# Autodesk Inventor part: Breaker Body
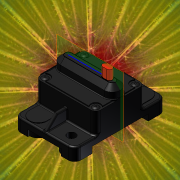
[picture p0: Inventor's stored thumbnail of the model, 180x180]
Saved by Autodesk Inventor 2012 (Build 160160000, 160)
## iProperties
Shininess: 64.0
Angle Display Precision: 2
Document Length Units: 11272
Document Angle Units: 11279
Document Time Units: 11290
Document Mass Units: 11286
Document Length Units Precision: 3
Document Angle Units Precision: 2
Compacted: False
Created: 2004-01
Part Number: Breaker Body
Material: Phenolic
Document SubType Name: Modeling
Designer: t8558es
Density: 1 g/cm^3
Density: 0.0
Volumn: 0.0
Area: 0.0
PropertySet Name: Model Information
Control State: 0
Master: False
Checked Out: False
Author: t8558es
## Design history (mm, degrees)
sketch "Sketch1"
  geometry: L1 (-24.13, 36.703)-(24.13, 36.703); L2 (24.13, 36.703)-(24.13, -36.703); L3 (24.13, -36.703)-(-24.13, -36.703); L4 (-24.13, -36.703)-(-24.13, 36.703); 1 further point
  constraints: 8 end point, 2 parallel, 1 horizontal, 1 perpendicular, 1 other
  dimensions: "d0" = 48.26 distance of L1.start L1.end; "d1" = 73.406 distance of L1.end L2.end; "d2" = 24.13 distance from line of point (0, 0) L4 (= 0.5 x d0); "d3" = 36.703 distance from line of L3 point (0, 0) (= 0.5 x d1)
extrude "Extrusion1" new body sketch "Sketch1" distance "d4" = 5.08; taper "d5" = 0 deg
fillet "Fillet1" dims "d6" = 5.08
sketch "Sketch2"
  geometry: L1 (24.13, 31.623)-(24.13, -31.623) reference; L2 (-24.13, -31.623)-(-24.13, 31.623) reference; L3 (-24.13, 19.685)-(24.13, 19.685); L4 (-24.13, -19.685)-(24.13, -19.685); L5 (0, 0)-(0, 19.685); L6 (0, 0)-(0, -19.685)
  constraints: 8 end point, 4 point on line, 2 midpoint, 1 collinear, 1 parallel, 1 perpendicular, 1 other
  dimensions: "d7" = 39.37 distance between parallel lines of L4 L3
extrude "Extrusion2" join sketch "Sketch2" distance "d8" = 17.526; taper "d9" = 0 deg
fillet "Fillet2" dims "d10" = 3.81
sketch "Sketch3"
  geometry: L1 (-19.05, 36.703)-(19.05, 36.703) reference; L2 (-24.13, 15.875)-(-24.13, 31.623) reference; 1 further point
  dimensions: "d11" = 10.795 distance from line of point (-13.335, 28.321) L2; "d12" = 8.382 distance from line of L1 point (-13.335, 28.321)
hole "Hole1" sketch "Sketch3" at (-13.335, 28.321) diameter "d13" = 6.604; stored, may be unused: countersink angle "d17" = 82 deg, drill point angle "d19" = 118 deg; dims "d14" = 12.7, "d15" = 9.525, "d16" = 6.35, "d18" = 19.05
sketch "Sketch5"
  geometry: L1 (24.13, -31.623)-(24.13, 31.623) reference; L2 (19.05, 36.703)-(-19.05, 36.703) reference; L3 (13.335, 35.433)-(13.335, 36.703); L4 (17.391, 22.479)-(24.13, 22.479); C1 r 3.302 at (13.335, 28.321) reference; A1 r 5.08 centre (19.05, 31.623) between (24.13, 31.623) and (19.05, 36.703) reference; A2 r 7.112 centre (13.335, 28.321) between (13.335, 35.433) and (17.391, 22.479)
  constraints: 4 end point, 3 point on line, 2 perpendicular, 2 point on circle, 1 centre point, 1 coincident
  dimensions: "d20" = 14.224 diameter of A2; "d21" = 14.224 distance between parallel lines of L2 L4
extrude "Extrusion3" join sketch "Sketch5" distance "d23" = 5.08; taper "d24" = 0 deg
mirror "Mirror3"
mirror "Mirror4"
sketch "Sketch6"
  geometry: L1 (24.13, 15.875)-(24.13, -15.875) reference; L2 (-24.13, -15.875)-(-24.13, 15.875) reference; L3 (-24.13, 6.477)-(24.13, 6.477); L4 (-24.13, -6.477)-(24.13, -6.477); L5 (0, 0)-(0, -6.477); L6 (0, 0)-(0, 6.477)
  constraints: 8 end point, 4 point on line, 2 midpoint, 2 perpendicular, 1 collinear, 1 other
  dimensions: "d25" = 12.954 distance between parallel lines of L4 L3
extrude "Extrusion4" join sketch "Sketch6" distance "d26" = 8.89; taper "d27" = 0 deg
fillet "Fillet3" dims "d28" = 6.477
chamfer "Chamfer1" distance "d29" = 3.81; stored, may be unused: second distance "d30" = 3.81, angle "d47" = 45 deg
sketch "Sketch7"
  geometry: L1 (-17.653, 2.159)-(-10.033, 2.159); L2 (-10.033, 2.159)-(-10.033, -2.159); L3 (-10.033, -2.159)-(-17.653, -2.159); L4 (-17.653, -2.159)-(-17.653, 2.159); A1 r 2.667 centre (-17.653, 0) between (-17.653, 2.667) and (-17.653, -2.667) reference
  constraints: 8 end point, 2 parallel, 1 horizontal, 1 midpoint, 1 perpendicular
  dimensions: "d31" = 4.318 distance of L1.end L2.end; "d32" = 7.62 distance of L2.end L3.end; "d33" = 2.159 distance from line of L1 A1.centre (= 0.5 x d31)
extrude "Button" join sketch "Sketch7" distance "d34" = 7.62; taper "d35" = 0 deg
fillet "Fillet4" dims "d36" = 2.159 (= 0.5 x d31)
fillet "Fillet7" dims "d46" = 1.27
sketch "Sketch8"
  geometry: L1 (-20.32, 19.685)-(20.32, 19.685) reference; L2 (-19.05, 36.703)-(19.05, 36.703) reference; L3 (-1.27, 36.703)-(-1.27, 19.685); L4 (1.27, 36.703)-(1.27, 19.685); 1 further point
  constraints: 4 end point, 4 point on line, 1 parallel, 1 perpendicular, 1 other
  dimensions: "d37" = 2.54 distance between parallel lines of L4 L3; "d38" = 1.27 distance from line of point (0, 0) L4 (= 0.5 x d37)
extrude "Extrusion6" join sketch "Sketch8" distance "d39" = 8.89; taper "d40" = 0 deg
chamfer "Chamfer2" distance "d41" = 8.89; stored, may be unused: second distance "d42" = 8.89, angle "d48" = 45 deg
fillet "Fillet5" dims "d43" = 1.27
mirror "Mirror5"
fillet "Fillet6" dims "d44" = 1.27, "d45" = 0.635
sketch "Sketch9"
  geometry: L1 (24.13, 2.938)-(24.13, 15.875) reference; L2 (-20.32, 19.685)-(20.32, 19.685) reference; L3 (-24.13, 2.938)-(-24.13, 15.875) reference; L4 (-22.86, 4.844)-(22.86, 4.844); L5 (22.86, 4.844)-(22.86, 18.415); L6 (22.86, 18.415)-(-22.86, 18.415); L7 (-22.86, 18.415)-(-22.86, 4.844); L8 (24.13, 2.938)-(24.13, 15.875) reference; L9 (-20.32, 19.685)-(20.32, 19.685) reference; L10 (-24.13, 2.938)-(-24.13, 15.875) reference; L11 (17.653, 7.112)-(-17.653, 7.112) reference; L12 (24.13, 2.938)-(24.129, 15.972); L13 (20.32, 19.685)-(-20.32, 19.685); L14 (-24.13, 15.875)-(-24.13, 2.938); A1 r 3.81 centre (20.32, 15.875) between (24.13, 15.875) and (20.32, 19.685) reference; A2 r 3.81 centre (-20.32, 15.875) between (-20.32, 19.685) and (-24.13, 15.875) reference; A3 r 7.112 centre (-17.653, 0) between (-17.653, 7.112) and (-24.13, 2.938) reference; A4 r 3.81 centre (-20.32, 15.875) between (-20.32, 19.685) and (-24.13, 15.875); A5 r 3.81 centre (20.32, 15.875) between (24.129, 15.972) and (20.32, 19.685); A6 r 7.112 centre (17.653, 0) between (24.13, 2.938) and (17.653, 7.112) reference; A7 r 3.81 centre (20.32, 15.875) between (24.13, 15.875) and (20.32, 19.685) reference; A8 r 3.81 centre (-20.32, 15.875) between (-20.32, 19.685) and (-24.13, 15.875) reference; A9 r 7.112 centre (-17.653, 0) between (-17.653, 7.112) and (-24.13, 2.938) reference; A10 r 7.112 centre (17.653, 0) between (24.13, 2.938) and (22.86, 4.844); A11 r 3.81 centre (20.32, 15.875) between (24.13, 15.875) and (20.32, 19.685); A12 r 3.81 centre (-20.32, 15.875) between (-20.32, 19.685) and (-24.13, 15.875); A13 r 7.112 centre (-17.653, 0) between (-22.86, 4.844) and (-24.13, 2.938)
  constraints: 14 end point, 14 point on circle, 12 tangent, 6 centre point, 4 equal length, 3 concentric, 3 point on line, 2 coincident, 1 horizontal, 1 perpendicular
  dimensions: "d52" = 1.27 distance between parallel lines of L2 L6; "d53" = 1.27 distance between parallel lines of L1 L5; "d54" = 1.27 distance between parallel lines of L3 L7
extrude "Extrusion7" cut sketch "Sketch9" distance "d55" = 0.762; taper "d56" = 0 deg
sketch "Sketch10"
  geometry: L1 (-17.48, 18.415)-(17.48, 18.415) reference; C1 r 2.54 at (20.32, 15.875); C2 r 2.54 at (-20.32, 15.875); A1 r 3.81 centre (-20.32, 15.875) between (-22.86, 13.035) and (-17.48, 18.415) reference; A2 r 3.81 centre (20.32, 15.875) between (17.48, 18.415) and (22.86, 13.035) reference
  constraints: 2 centre point, 2 coincident, 1 tangent
  dimensions: "d57" = 5.08 diameter of C1; "d58" = 5.08 diameter of C2 (derived)
extrude "Extrusion8" join sketch "Sketch10" stored distance "d59" = 0.762; taper "d60" = 0 deg
fillet "Fillet8" dims "d61" = 2.54
sketch "Sketch11"
  geometry: L1 (-12.192, -2.159)-(-15.494, -2.159) reference; L2 (-15.494, 2.159)-(-12.192, 2.159) reference; L3 (-17.653, 2.667)-(17.653, 2.667) reference; L4 (17.653, -2.667)-(-17.653, -2.667) reference; L5 (17.653, 0)-(-16.76, 0); A1 r 2.159 centre (-15.494, 0) between (-15.494, 2.159) and (-15.494, -2.159) reference; A2 r 2.159 centre (-12.192, 0) between (-12.192, -2.159) and (-12.192, 2.159) reference; A3 r 2.667 centre (-17.653, 0) between (-17.653, 2.667) and (-17.653, -2.667) reference; A4 r 2.667 centre (17.653, 0) between (17.653, -2.667) and (17.653, 2.667) reference
  constraints: 2 end point, 1 parallel
workplane "Work Plane1"
node "Sketch12"
workplane "Work Plane2"
mirror "Mirror7"
fillet "Fillet9" dims "d63" = 2.54
sketch "Sketch13"
  geometry: L1 (1.719, 35.433)-(19.05, 35.433) reference; L2 (20.32, 20.955)-(1.905, 20.955) reference; L3 (13.335, 28.321)-(21.7, 28.321); L4 (13.335, 28.321)-(2.495, 28.321); L5 (6.223, 28.321)-(6.223, 20.955); L6 (20.447, 28.321)-(20.32, 20.955); C1 r 3.302 at (13.335, 28.321) reference; C2 r 6.35 at (13.335, 28.321) reference; C3 r 6.35 at (13.335, 28.321); A1 r 7.112 centre (13.335, 28.321) between (6.223, 28.321) and (20.447, 28.321)
  constraints: 8 end point, 3 point on line, 2 centre point, 2 coincident, 2 point on circle, 2 tangent, 1 collinear, 1 concentric, 1 parallel, 1 perpendicular
extrude "Extrusion9" join sketch "Sketch13" distance "d64" = 0.508; taper "d65" = 0 deg
sketch "Sketch14"
  geometry: L1 (-1.719, -35.433)-(-19.05, -35.433) reference; L2 (-20.32, -20.955)-(-1.905, -20.955) reference; L3 (-13.335, -28.321)-(-21.971, -28.321); L4 (-13.335, -28.321)-(-2.859, -28.321); L5 (-6.223, -28.321)-(-6.223, -20.955); L6 (-20.447, -28.321)-(-20.447, -20.953); C1 r 3.302 at (-13.335, -28.321) reference; C2 r 6.35 at (-13.335, -28.321) reference; A1 r 5.08 centre (-20.32, -15.875) between (-22.86, -20.274) and (-20.32, -20.955) reference; A2 r 7.112 centre (-13.335, -28.321) between (-6.223, -28.321) and (-20.447, -28.321)
  constraints: 8 end point, 3 point on circle, 3 point on line, 3 tangent, 2 parallel, 1 centre point, 1 coincident, 1 collinear, 1 perpendicular
extrude "Extrusion10" join sketch "Sketch14" distance "d66" = 0.508; taper "d67" = 0 deg
sketch "Sketch15"
  geometry: L1 (-5.47, -21.284)-(-2.721, -21.284); L2 (-2.721, -21.284)-(-2.721, -48.102); L3 (-2.721, -48.102)-(-5.47, -48.102); L4 (-5.47, -48.102)-(-5.47, -21.284)
  constraints: 2 other
emboss "Emboss1" sketch "Sketch15" dims "d7" = 39.37, "d68" = 0.254, "d69" = 0
sketch "Sketch16"
  geometry: C1 r 1.27 at (19.05, -31.623); A1 r 3.81 centre (19.05, -31.623) between (19.05, -35.433) and (22.86, -31.623) reference
  constraints: 1 centre point, 1 coincident
  dimensions: "d84" = 2.54 diameter of C1
extrude "Extrusion11" cut sketch "Sketch16" distance "d70" = 0.0254; taper "d71" = 0 deg
sketch "Sketch17"
  geometry: L1 (5.335, 21.387)-(2.781, 21.387); L2 (2.781, 21.387)-(2.781, 34.472); L3 (2.781, 34.472)-(5.335, 34.472); L4 (5.335, 34.472)-(5.335, 21.387)
  constraints: 2 other
emboss "Emboss2" sketch "Sketch17" dims "d7" = 39.37, "d72" = 0.254, "d73" = 0
sketch "Sketch18"
  geometry: L1 (-17.48, -18.415)-(17.48, -18.415) reference; L2 (-19.778, -11.408)-(-21.696, -11.408); L3 (-22.23, -10.874)-(-22.23, -8.727); L4 (-21.299, -8.371)-(-19.38, -10.519); A1 r 0.051 centre (-22.179, -7.463) between (-22.141, -7.429) and (-22.23, -7.463); A2 r 0.533 centre (-21.696, -8.727) between (-21.299, -8.371) and (-22.23, -8.727); A3 r 0.533 centre (-21.696, -10.874) between (-22.23, -10.874) and (-21.696, -11.408); A4 r 0.533 centre (-19.778, -10.874) between (-19.778, -11.408) and (-19.38, -10.519)
  constraints: 8 point on circle, 8 tangent, 6 end point, 4 centre point, 2 equal radius, 2 point on line, 1 parallel, 1 perpendicular
  dimensions: "d74" = 0.0508 radius of A1; "d75" = 0.5334 radius of A2
extrude "Extrusion12" join sketch "Sketch18" distance "d76" = 0.254; taper "d77" = 0 deg
sketch "Sketch19"
  geometry: L1 (-1.115, -8.947)-(21.602, -8.947); L2 (21.602, -8.947)-(21.602, -19.394); L3 (21.602, -19.394)-(-1.115, -19.394); L4 (-1.115, -19.394)-(-1.115, -8.947)
  constraints: 2 other
emboss "Emboss3" sketch "Sketch19" dims "d7" = 39.37, "d78" = 0.0254, "d79" = 0
sketch "Sketch20"
  geometry: L1 (-12.953, 17.904)-(12.174, 17.904); L2 (12.174, 17.904)-(12.174, 6.102); L3 (12.174, 6.102)-(-12.953, 6.102); L4 (-12.953, 6.102)-(-12.953, 17.904)
  constraints: 2 other
emboss "Emboss4" sketch "Sketch20" dims "d7" = 39.37, "d80" = 0.0254, "d81" = 0
sketch "Sketch21"
  geometry: L1 (3.133, 14.535)-(8.084, 14.535); L2 (8.084, 14.535)-(8.084, 10.142); L3 (8.084, 10.142)-(3.133, 10.142); L4 (3.133, 10.142)-(3.133, 14.535)
  constraints: 2 other
emboss "Emboss5" sketch "Sketch21" dims "d7" = 39.37, "d82" = 0.0254, "d83" = 0
sketch "Sketch22"
  geometry: C1 r 1.27 at (-19.05, 31.623); A1 r 3.81 centre (-19.05, 31.623) between (-19.05, 35.433) and (-22.86, 31.623) reference
  constraints: 1 centre point, 1 coincident
  dimensions: "d85" = 2.54 diameter of C1
extrude "Extrusion13" cut sketch "Sketch22" distance "d86" = 0.0254; taper "d87" = 0 deg
body "Solid1"
node "Projected Loop1"
node "Reference1"
node "Reference2"
other parameters: "d62" = 90 deg
